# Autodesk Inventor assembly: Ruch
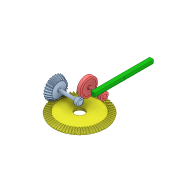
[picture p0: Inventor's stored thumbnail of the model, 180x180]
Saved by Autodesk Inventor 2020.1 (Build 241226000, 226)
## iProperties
Created: 2005-12
Part Number: Ruch
Document SubType Name: Assembly
Designer: F.Stasiak
Manager: www.cadconsulting.pl
Company: Fabian Stasiak CAD Consulting
Author: F.Stasiak
Subject: Zbiór ćwiczeń. Autodesk Inventor 2020. Kurs podstawowy
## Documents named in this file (6)
- C:\2020_Kurs_podstawowy\R6 Zespoły\Wiązania\Przekładnia I\Ruch.iam
- C:\2020_Kurs_podstawowy\R6 Zespoły\Wiązania\Przekładnia I\Belka.ipt
- C:\2020_Kurs_podstawowy\R6 Zespoły\Wiązania\Przekładnia I\GEAR2 008Q2VBY.ipt
- C:\2020_Kurs_podstawowy\R6 Zespoły\Wiązania\Przekładnia I\GEAR2 008Q2YCY.ipt
- C:\2020_Kurs_podstawowy\R6 Zespoły\Wiązania\Przekładnia I\OSIE1.ipt
- C:\2020_Kurs_podstawowy\R6 Zespoły\Wiązania\Przekładnia I\Rolka.ipt
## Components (5 placed, 5 different names)
1. OSIE1:1 — Równoległy:2, Zestawiający:6, Zestawiający:7, Zestawiający:9
2. Małe koło przekładni stożkowej 25/66, 4:1 — NAPĘD, Zestawiający:5, Równoległy:1, Zestawiający:6, Równoległy:3
3. Duże koło przekładni stożkowej 25/66, 4:2 — Zestawiający:7, Zestawiający:8
4. Rolka:1 — Równoległy:3, Zestawiający:9, Równoległy:4
5. Belka:1 — Równoległy:4, Zestawiający:12
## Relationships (11: Mate 6, Flush 4, Angle 1)
- NAPĘD [Angle]: Małe koło przekładni stożkowej 25/66, 4:1
- Zestawiający:5 [Mate]: Małe koło przekładni stożkowej 25/66, 4:1
- Równoległy:1 [Flush]: Małe koło przekładni stożkowej 25/66, 4:1
- Równoległy:2 [Flush]: OSIE1:1
- Zestawiający:6 [Mate]: OSIE1:1 ↔ Małe koło przekładni stożkowej 25/66, 4:1
- Zestawiający:7 [Mate]: OSIE1:1 ↔ Duże koło przekładni stożkowej 25/66, 4:2
- Zestawiający:8 [Mate]: Duże koło przekładni stożkowej 25/66, 4:2
- Równoległy:3 [Flush]: Małe koło przekładni stożkowej 25/66, 4:1 ↔ Rolka:1
- Zestawiający:9 [Mate]: OSIE1:1 ↔ Rolka:1
- Równoległy:4 [Flush]: Rolka:1 ↔ Belka:1
- Zestawiający:12 [Mate]: Belka:1
